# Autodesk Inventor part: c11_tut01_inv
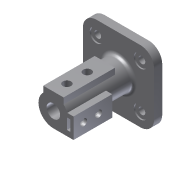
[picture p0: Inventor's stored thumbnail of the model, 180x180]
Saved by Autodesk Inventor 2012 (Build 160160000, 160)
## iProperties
Created: 2010-03
Part Number: c11_tut01_inv
Document SubType Name: Modeling
Designer: CADSoft
Density: 1 g/cm^3
Material: Default
Author: CADSoft
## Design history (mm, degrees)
sketch "Sketch1"
  geometry: 1 further point
sketch "Sketch2"
  geometry: L1 (32.5, 52.5)-(-32.5, 52.5); L2 (-52.5, 32.5)-(-52.5, -32.5); L3 (-32.5, -52.5)-(32.5, -52.5); L4 (52.5, -32.5)-(52.5, 32.5); A1 r 20 centre (32.5, 32.5) between (52.5, 32.5) and (32.5, 52.5); A2 r 20 centre (-32.5, 32.5) between (-32.5, 52.5) and (-52.5, 32.5); A3 r 20 centre (-32.5, -32.5) between (-52.5, -32.5) and (-32.5, -52.5); A4 r 20 centre (32.5, -32.5) between (32.5, -52.5) and (52.5, -32.5); 4 further points
  constraints: 8 end point, 8 point on circle, 8 tangent, 6 point on line, 4 centre point, 3 equal radius, 3 perpendicular, 1 other
  dimensions: "d3" = 105 distance of point (52.5, 52.5) point (-52.5, 52.5); "d4" = 105 distance of point (52.5, -52.5) point (52.5, 52.5); "d6" = 52.5 distance from line of L1 point (0, 0); "d7" = 52.5 distance from line of L4 point (0, 0); "d8" = 20 radius of A1
extrude "Extrusion1" new body sketch "Sketch2" distance "d9" = 12; taper "d10" = 0 deg
hole "Hole1" diameter "d13" = 10; stored, may be unused: countersink angle "d17" = 90 deg, drill point angle "d19" = 118 deg; dims "d11" = 10, "d12" = 10, "d14" = 6, "d15" = 20, "d16" = 2, "d18" = 8
hole "Hole2" diameter "d22" = 10; stored, may be unused: countersink angle "d26" = 90 deg, drill point angle "d28" = 118 deg; dims "d20" = 10, "d21" = 10, "d23" = 6, "d24" = 20, "d25" = 2, "d27" = 8
hole "Hole3" diameter "d31" = 10; stored, may be unused: countersink angle "d35" = 90 deg, drill point angle "d37" = 118 deg; dims "d29" = 10, "d30" = 10, "d32" = 6, "d33" = 20, "d34" = 2, "d36" = 8
hole "Hole4" diameter "d40" = 10; stored, may be unused: countersink angle "d44" = 90 deg, drill point angle "d46" = 118 deg; dims "d38" = 10, "d39" = 10, "d41" = 6, "d42" = 20, "d43" = 2, "d45" = 8
sketch "Sketch3"
  geometry: C1 r 22 at (0, 0); 1 further point
  constraints: 1 centre point, 1 coincident
  dimensions: "d47" = 44 diameter of C1
extrude "Extrusion2" join sketch "Sketch3" distance "d48" = 96; taper "d49" = 0 deg
sketch "Sketch4"
  geometry: L1 (-15, 25)-(15, 25); L2 (15, 25)-(15, 16.093); L3 (-14.745, 16.328)-(-15, 16.093); L4 (-15, 16.093)-(-15, 25); A1 r 22 centre (0, 0) between (15, 16.093) and (-15, 16.093); 1 further point
  constraints: 8 end point, 4 point on circle, 2 vertical, 1 centre point, 1 coincident
  dimensions: "d50" = 30 distance of L1.start L1.end; "d52" = 15 distance from line of point (0, 0) L4; "d53" = 25 distance from line of point (0, 0) L1
extrude "Extrusion3" join sketch "Sketch4" distance "d54" = 76; taper "d55" = 0 deg
sketch "Sketch5"
  geometry: L1 (0, -22)-(29.709, -22); L2 (29.709, -22)-(29.709, 8); L3 (29.709, 8)-(20.494, 8); A1 r 22 centre (0, 0) between (0, -22) and (20.494, 8); 1 further point
  constraints: 6 end point, 2 point on circle, 1 centre point, 1 coincident
  dimensions: "d61" = 30 distance of L1.end L2.end
extrude "Extrusion4" join sketch "Sketch5" distance "d62" = 57; taper "d63" = 0 deg
sketch "Sketch6"
  geometry: L1 (20, 2)-(25, 2); L2 (25, 2)-(25, -14); L3 (25, -14)-(20, -14); L4 (20, -14)-(20, 2); A1 r 22 centre (0, 0) between (20.494, 8) and (15, 16.093) reference
  constraints: 8 end point
  dimensions: "d64" = 2 distance from line of A1.centre L1; "d66" = 25 distance from line of L2 A1.centre; "d67" = 5 distance of L2.end L3.end; "d68" = 16 distance of L1.end L2.end
extrude "Extrusion5" cut sketch "Sketch6" distance "d69" = 50; taper "d70" = 0 deg
hole "Hole5" diameter "d73" = 20; stored, may be unused: countersink angle "d77" = 90 deg, drill point angle "d79" = 0 deg; dims "d71" = 10, "d72" = 10, "d74" = 6, "d75" = 20, "d76" = 2, "d78" = 96
hole "Hole6" diameter "d82" = 12; stored, may be unused: countersink angle "d86" = 90 deg, drill point angle "d88" = 118 deg; dims "d80" = 20, "d81" = 15, "d83" = 6, "d84" = 20, "d85" = 2, "d87" = 96
hole "Hole7" diameter "d91" = 12; stored, may be unused: countersink angle "d95" = 90 deg, drill point angle "d97" = 118 deg; dims "d89" = 15, "d90" = 50, "d92" = 6, "d93" = 20, "d94" = 2, "d96" = 96
hole "Hole8" diameter "d100" = 10; stored, may be unused: countersink angle "d104" = 90 deg, drill point angle "d106" = 118 deg; dims "d98" = 15, "d99" = 15, "d101" = 6, "d102" = 20, "d103" = 2, "d105" = 96
hole "Hole9" diameter "d109" = 10; stored, may be unused: countersink angle "d113" = 90 deg, drill point angle "d115" = 118 deg; dims "d107" = 15, "d108" = 37, "d110" = 6, "d111" = 20, "d112" = 2, "d114" = 96
fillet "Fillet1" dims "d116" = 5
body "Solid1"
